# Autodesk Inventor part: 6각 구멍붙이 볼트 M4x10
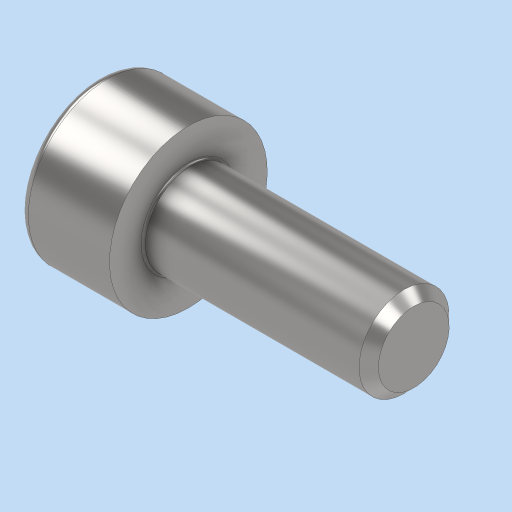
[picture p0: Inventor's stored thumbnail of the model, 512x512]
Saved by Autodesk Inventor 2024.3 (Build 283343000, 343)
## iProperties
Created: 2025-11
Part Number: 6각 구멍붙이 볼트 M4x10
Material: 강철, 연강
Description: 6각머리 태핑 나사
Document SubType Name: Modeling
Designer: PC2-03
Density: 7.85 g/cm^3
Appearance: 기본값
Author: jhkim
Sending System: Autodesk Inventor 2026
Preprocessor: ST-DEVELOPER v20.1
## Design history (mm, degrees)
feature "Solid1"
node "솔리드1"
